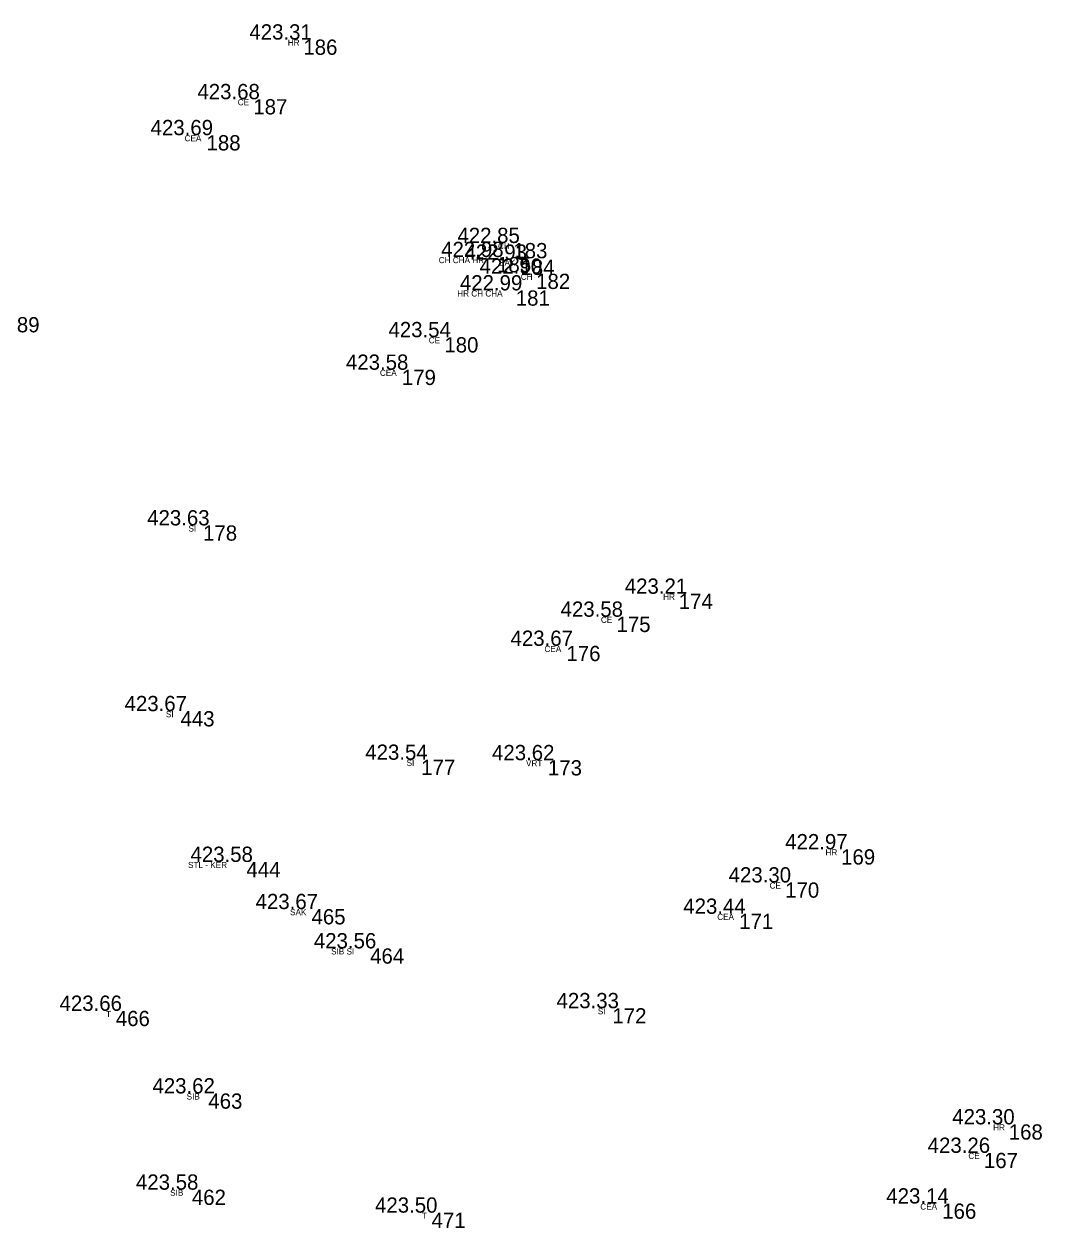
# Model space of a CAD drawing. Extents: x -639373 to -639057, y -1138651 to -1138359.
# Drawn here: x -639183.3 to -639133.3, y -1138586.4 to -1138527.2 of the extents above; entities that cross this region are included whole.
import ezdxf

# ---------------------------------------------------------------- set-up
doc = ezdxf.new("R2010")
doc.units = 0
for name, color, linetype in [('Vrstva 11', 7, 'Continuous'), ('Vrstva 12', 7, 'Continuous'), ('Vrstva 13', 7, 'Continuous'), ('Vrstva 14', 7, 'Continuous'), ('Vrstva 57', 7, 'Continuous')]:
    doc.layers.add(name, color=color, linetype=linetype)

msp = doc.modelspace()

# ---------------------------------------------------------------- linework, layer by layer
at = {"layer": 'Vrstva 11'}
for p, q in [((-639169.89, -1138527.94), (-639169.89, -1138527.94)), ((-639172.35, -1138530.87), (-639172.35, -1138530.87)), ((-639174.65, -1138532.64), (-639174.65, -1138532.64)), ((-639159.57, -1138537.94), (-639159.57, -1138537.94)), ((-639160.37, -1138538.63), (-639160.37, -1138538.63)), ((-639159.22, -1138538.76), (-639159.22, -1138538.76)), ((-639158.45, -1138539.45), (-639158.45, -1138539.45)), ((-639159.45, -1138540.27), (-639159.45, -1138540.27)), ((-639162.96, -1138542.57), (-639162.96, -1138542.57)), ((-639165.05, -1138544.17), (-639165.05, -1138544.17)), ((-639174.82, -1138551.82), (-639174.82, -1138551.82)), ((-639151.44, -1138555.18), (-639151.44, -1138555.18)), ((-639154.5, -1138556.31), (-639154.5, -1138556.31)), ((-639156.96, -1138557.74), (-639156.96, -1138557.74)), ((-639175.93, -1138560.95), (-639175.93, -1138560.95)), ((-639164.1, -1138563.34), (-639164.1, -1138563.34)), ((-639157.87, -1138563.36), (-639157.87, -1138563.36)), ((-639143.46, -1138567.74), (-639143.46, -1138567.74)), ((-639172.69, -1138568.36), (-639172.69, -1138568.36)), ((-639146.21, -1138569.37), (-639146.21, -1138569.37)), ((-639169.49, -1138570.68), (-639169.49, -1138570.68)), ((-639148.47, -1138570.91), (-639148.47, -1138570.91)), ((-639166.61, -1138572.61), (-639166.61, -1138572.61)), ((-639179.11, -1138575.68), (-639179.11, -1138575.68)), ((-639154.7, -1138575.55), (-639154.7, -1138575.55)), ((-639174.56, -1138579.74), (-639174.56, -1138579.74)), ((-639135.22, -1138581.26), (-639135.22, -1138581.26)), ((-639136.44, -1138582.66), (-639136.44, -1138582.66)), ((-639175.37, -1138584.47), (-639175.37, -1138584.47)), ((-639138.49, -1138585.15), (-639138.49, -1138585.15)), ((-639163.59, -1138585.6), (-639163.59, -1138585.6))]:
    msp.add_line(p, q, dxfattribs=at)

# ---------------------------------------------------------------- texts
at = {"layer": 'Vrstva 12'}
for s, p in [('422.85 ', (-639162.04, -1138537.94)), ('422.98 ', (-639162.839, -1138538.63)), ('422.90 ', (-639160.949, -1138539.45)), ('422.99 ', (-639161.919, -1138540.27)), ('423.58 ', (-639175.159, -1138568.36)), ('423.67 ', (-639171.959, -1138570.68))]:
    msp.add_text(s, height=0.75, dxfattribs=at).set_placement(p)
at = {"layer": 'Vrstva 13'}
for s, p in [(' 186', (-639169.89, -1138528.69)), (' 187', (-639172.35, -1138531.62)), (' 188', (-639174.65, -1138533.39)), (' 183', (-639159.57, -1138538.69)), (' 185', (-639160.37, -1138539.38)), (' 184', (-639159.22, -1138539.51)), (' 182', (-639158.45, -1138540.2)), (' 181', (-639159.45, -1138541.02)), (' 189', (-639184.53, -1138542.33)), (' 180', (-639162.96, -1138543.32)), (' 179', (-639165.05, -1138544.92)), (' 178', (-639174.82, -1138552.57)), (' 174', (-639151.44, -1138555.93)), (' 175', (-639154.5, -1138557.06)), (' 176', (-639156.96, -1138558.49)), (' 443', (-639175.93, -1138561.7)), (' 177', (-639164.1, -1138564.09)), (' 173', (-639157.87, -1138564.11)), (' 169', (-639143.46, -1138568.49)), (' 444', (-639172.69, -1138569.11)), (' 170', (-639146.21, -1138570.12)), (' 465', (-639169.49, -1138571.43)), (' 171', (-639148.47, -1138571.66)), (' 464', (-639166.61, -1138573.36)), (' 466', (-639179.11, -1138576.43)), (' 172', (-639154.7, -1138576.3)), (' 463', (-639174.56, -1138580.49)), (' 168', (-639135.22, -1138582.01)), (' 167', (-639136.44, -1138583.41)), (' 462', (-639175.37, -1138585.22)), (' 166', (-639138.49, -1138585.9)), (' 471', (-639163.59, -1138586.35))]:
    msp.add_text(s, height=0.75, dxfattribs=at).set_placement(p)
at = {"layer": 'Vrstva 14'}
for s, p in [('423.31 ', (-639172.265, -1138527.94)), ('423.68 ', (-639174.819, -1138530.87)), ('423.69 ', (-639177.119, -1138532.64)), ('422.93 ', (-639161.689, -1138538.76)), ('423.54 ', (-639165.429, -1138542.57)), ('423.58 ', (-639167.519, -1138544.17)), ('423.63 ', (-639177.289, -1138551.82)), ('423.21 ', (-639153.815, -1138555.18)), ('423.58 ', (-639156.969, -1138556.31)), ('423.67 ', (-639159.429, -1138557.74)), ('423.67 ', (-639178.399, -1138560.95)), ('423.54 ', (-639166.569, -1138563.34)), ('423.62 ', (-639160.339, -1138563.36)), ('422.97 ', (-639145.929, -1138567.74)), ('423.30 ', (-639148.709, -1138569.37)), ('423.44 ', (-639150.939, -1138570.91)), ('423.56 ', (-639169.096, -1138572.61)), ('423.66 ', (-639181.596, -1138575.68)), ('423.33 ', (-639157.169, -1138575.55)), ('423.62 ', (-639177.029, -1138579.74)), ('423.30 ', (-639137.719, -1138581.26)), ('423.26 ', (-639138.926, -1138582.66)), ('423.58 ', (-639177.839, -1138584.47)), ('423.14 ', (-639140.959, -1138585.15)), ('423.50 ', (-639166.089, -1138585.6))]:
    msp.add_text(s, height=0.75, dxfattribs=at).set_placement(p)
at = {"layer": 'Vrstva 57'}
for s, p in [('HR', (-639170.379, -1138528.24)), ('CE', (-639172.838, -1138531.17)), ('CEA', (-639175.45, -1138532.94)), ('CH', (-639160.045, -1138538.24)), ('CH CHA HR', (-639162.959, -1138538.93)), ('SAK', (-639159.995, -1138539.06)), ('CH', (-639158.925, -1138539.75)), ('HR CH CHA', (-639162.05, -1138540.57)), ('CE', (-639163.448, -1138542.87)), ('CEA', (-639165.85, -1138544.47)), ('SI', (-639175.258, -1138552.12)), ('HR', (-639151.929, -1138555.48)), ('CE', (-639154.988, -1138556.61)), ('CEA', (-639157.76, -1138558.04)), ('SI', (-639176.368, -1138561.25)), ('SI', (-639164.538, -1138563.64)), ('VRT', (-639158.67, -1138563.66)), ('HR', (-639143.949, -1138568.04)), ('STL - KER', (-639175.279, -1138568.66)), ('CE', (-639146.698, -1138569.67)), ('SAK', (-639170.265, -1138570.98)), ('CEA', (-639149.27, -1138571.21)), ('SIB SI', (-639168.248, -1138572.91)), ('T', (-639179.31, -1138575.98)), ('SI', (-639155.138, -1138575.85)), ('SIB', (-639175.349, -1138580.04)), ('HR', (-639135.709, -1138581.56)), ('CE', (-639136.927, -1138582.96)), ('SIB', (-639176.159, -1138584.77)), ('CEA', (-639139.29, -1138585.45)), ('T', (-639163.79, -1138585.9))]:
    msp.add_text(s, height=0.3, dxfattribs=at).set_placement(p)

doc.saveas('drawing.dxf')
